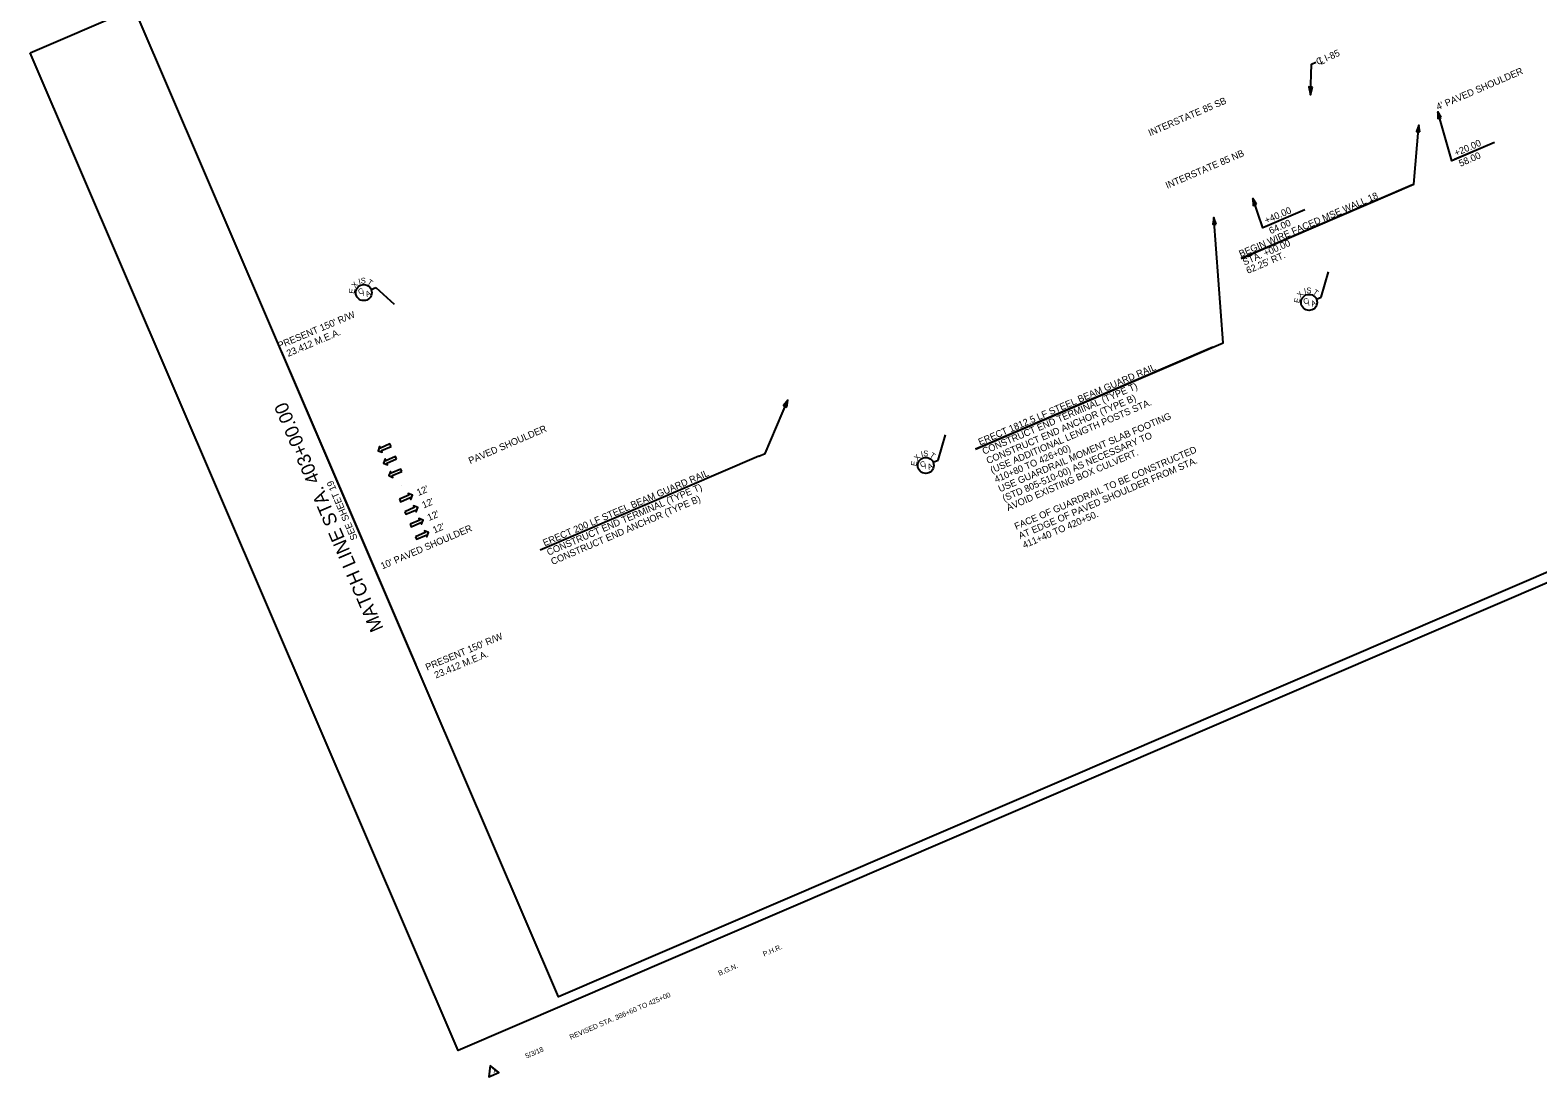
# Model space of a CAD drawing. Extents: x 1618233 to 1620283, y 1101130 to 1102832.
# Drawn here: x 1618233 to 1619562, y 1101130 to 1102053 of the extents above; entities that cross this region are included whole.
import ezdxf

# ---------------------------------------------------------------- set-up
doc = ezdxf.new("R2010")
doc.units = 0
for name, color, linetype in [('RD_DTM_BkLn1', 7, 'Continuous'), ('RD_EX_BldgApp', 7, 'Continuous'), ('RD_EX_DV_TX_Gov', 7, 'Continuous'), ('RD_EX_Fence_Other', 7, 'Continuous'), ('RD_EX_Misc', 7, 'Continuous'), ('RD_EX_Misc_Golf_Teebox', 7, 'Continuous'), ('RD_EX_RailRoad', 7, 'Continuous'), ('RD_EX_VEG', 7, 'Continuous'), ('RD_HC_Data', 7, 'Continuous')]:
    doc.layers.add(name, color=color, linetype=linetype)

msp = doc.modelspace()

# ---------------------------------------------------------------- linework, layer by layer
at = {"layer": 'RD_DTM_BkLn1'}
for p, q in [((1619275.9, 1101773.3), (1619066.6, 1101683.5)), ((1618875.6, 1101677.3), (1618682.7, 1101594.5))]:
    msp.add_line(p, q, dxfattribs=at)
for points in [[(1619066.6, 1101683.5), (1619284.9, 1101777.2), (1619276.9, 1101887.6)], [(1618875.6, 1101677.3), (1618881.1, 1101679.7), (1618901.1, 1101726.7)]]:
    msp.add_lwpolyline(points, dxfattribs=at)
for points in [[(1619278.9, 1101881.9), (1619276.9, 1101887.6), (1619275.8, 1101881.7)], [(1618900.2, 1101720.7), (1618901.1, 1101726.7), (1618897.4, 1101721.9)]]:
    msp.add_lwpolyline(points, close=True, dxfattribs=at)
at = {"layer": 'RD_EX_DV_TX_Gov'}
msp.add_lwpolyline([(1619361.9, 1101995.8), (1619362.8, 1102022.7), (1619366.8, 1102024.5)], dxfattribs=at)
msp.add_lwpolyline([(1619363.8, 1102002.7), (1619360.4, 1102002.8), (1619361.9, 1101995.8)], close=True, dxfattribs=at)
at = {"layer": 'RD_EX_Fence_Other'}
msp.add_lwpolyline([(1618233.1, 1102032.7), (1619772.4, 1102693.3), (1620149.6, 1101814.3), (1618610.4, 1101153.7)], close=True, dxfattribs=at)
at = {"layer": 'RD_EX_Misc'}
for points in [[(1618551.4, 1101685.9), (1618550.4, 1101688.1), (1618542, 1101684.5), (1618541.3, 1101686), (1618539.9, 1101682.2), (1618543.6, 1101680.8), (1618542.9, 1101682.3)], [(1618556.1, 1101674.9), (1618555.2, 1101677.1), (1618546.7, 1101673.4), (1618546.1, 1101674.9), (1618544.6, 1101671.2), (1618548.3, 1101669.7), (1618547.7, 1101671.2)], [(1618560.8, 1101663.8), (1618559.9, 1101666), (1618551.5, 1101662.4), (1618550.8, 1101663.9), (1618549.3, 1101660.2), (1618553, 1101658.7), (1618552.4, 1101660.2)], [(1618558.7, 1101639.4), (1618559.6, 1101637.2), (1618568.1, 1101640.8), (1618568.7, 1101639.3), (1618570.2, 1101643), (1618566.5, 1101644.5), (1618567.1, 1101643)], [(1618563.4, 1101628.4), (1618564.4, 1101626.2), (1618572.8, 1101629.8), (1618573.4, 1101628.3), (1618574.9, 1101632), (1618571.2, 1101633.5), (1618571.8, 1101632)], [(1618568.1, 1101617.4), (1618569.1, 1101615.2), (1618577.5, 1101618.8), (1618578.2, 1101617.3), (1618579.6, 1101621), (1618575.9, 1101622.5), (1618576.6, 1101621)], [(1618572.9, 1101606.3), (1618573.8, 1101604.1), (1618582.3, 1101607.8), (1618582.9, 1101606.3), (1618584.4, 1101610), (1618580.7, 1101611.5), (1618581.3, 1101610)]]:
    msp.add_lwpolyline(points, close=True, dxfattribs=at)
at = {"layer": 'RD_EX_Misc_Golf_Teebox'}
for p, q in [((1619524.3, 1101953.9), (1619488.9, 1101938.7)), ((1619451.9, 1101916.5), (1619300.9, 1101851.7)), ((1619357, 1101894.5), (1619321.5, 1101879.3)), ((1618560.5, 1101651.9), (1618560.5, 1101651.9))]:
    msp.add_line(p, q, dxfattribs=at)
for points in [[(1619524.3, 1101953.9), (1619486.6, 1101937.7), (1619474.2, 1101980.9)], [(1619300.9, 1101851.7), (1619453, 1101917), (1619457.4, 1101969.1)], [(1619357, 1101894.5), (1619320, 1101878.7), (1619311.1, 1101904.4)]]:
    msp.add_lwpolyline(points, dxfattribs=at)
for points in [[(1619477.3, 1101975.8), (1619474.2, 1101980.9), (1619474.3, 1101974.9)], [(1619458.5, 1101963.2), (1619457.4, 1101969.1), (1619455.4, 1101963.5)], [(1619314.5, 1101899.5), (1619311.1, 1101904.4), (1619311.5, 1101898.4)], [(1618638.6, 1101140.3), (1618637.6, 1101130.4), (1618646.5, 1101134.2)]]:
    msp.add_lwpolyline(points, close=True, dxfattribs=at)
at = {"layer": 'RD_EX_RailRoad'}
msp.add_lwpolyline([(1618327.6, 1102066.1), (1619552.6, 1102591.9), (1619566, 1102561.6), (1619719.7, 1102625.9), (1620077.3, 1101792.6), (1618698.9, 1101201)], close=True, dxfattribs=at)
msp.add_lwpolyline([(1618327.6, 1102066.1), (1619552.6, 1102591.9), (1619566, 1102561.6), (1619719.7, 1102625.9), (1620077.3, 1101792.6), (1618698.9, 1101201)], close=True, dxfattribs=at)
at = {"layer": 'RD_EX_VEG'}
msp.add_lwpolyline([(1618573.1, 1101494.1), (1618514, 1101631.9), (1618454.8, 1101769.8)], dxfattribs=at)
at = {"layer": 'RD_HC_Data'}
for p, q in [((1619371.4, 1101817.5), (1619378, 1101839.8)), ((1618533.8, 1101824.3), (1618538, 1101826.1)), ((1618538, 1101826.1), (1618554.1, 1101811.3)), ((1619367.2, 1101815.7), (1619371.4, 1101817.5)), ((1619033.6, 1101673.8), (1619040.2, 1101696.1)), ((1619029.3, 1101672), (1619033.6, 1101673.8))]:
    msp.add_line(p, q, dxfattribs=at)
for centre in [(1618527.3, 1101821.5), (1619360.7, 1101812.9), (1619022.8, 1101669.2)]:
    msp.add_circle(centre, 7.08, dxfattribs=at)

# ---------------------------------------------------------------- texts
at = {"layer": 'RD_DTM_BkLn1'}
for s, p in [('ERECT 1812.5 LF STEEL BEAM GUARD RAIL', (1619070.6, 1101686.8)), ('CONSTRUCT END TERMINAL (TYPE T)', (1619074.1, 1101678.6)), ('CONSTRUCT END ANCHOR (TYPE B)', (1619077.7, 1101670.3)), ('(USE ADDITIONAL LENGTH POSTS STA.', (1619081.2, 1101662)), ('USE GUARDRAIL MOMENT SLAB FOOTING', (1619088.3, 1101645.5)), ('(STD 805-510-00) AS NECESSARY TO ', (1619091.9, 1101637.2)), ('410+80 TO 426+00)', (1619084.8, 1101653.8)), ('AVOID EXISTING BOX CULVERT.', (1619095.4, 1101629)), ('FACE OF GUARDRAIL TO BE CONSTRUCTED', (1619102.5, 1101612.4)), ('AT EDGE OF PAVED SHOULDER FROM STA.', (1619106.1, 1101604.1)), ('ERECT 200 LF STEEL BEAM GUARD RAIL', (1618686.7, 1101597.9)), ('CONSTRUCT END TERMINAL (TYPE T)', (1618690.2, 1101589.6)), ('CONSTRUCT END ANCHOR (TYPE B)', (1618693.8, 1101581.4)), ('411+40 TO 420+50.', (1619109.6, 1101595.9))]:
    msp.add_text(s, height=6, rotation=23.2284, dxfattribs=at).set_placement(p)
at = {"layer": 'RD_EX_BldgApp'}
for s, p in [("PRESENT 150' R/W ", (1618453, 1101771.8)), ('  23.412 M.E.A.', (1618456.6, 1101763.1)), ("PRESENT 150' R/W ", (1618583.2, 1101488.3)), ('  23.412 M.E.A.', (1618586.9, 1101479.6))]:
    msp.add_text(s, height=6, rotation=22.7764, dxfattribs=at).set_placement(p)
at = {"layer": 'RD_EX_DV_TX_Gov'}
for s, p in [('C I-85', (1619368.4, 1102021.9)), ('L', (1619371.2, 1102022.2)), ('INTERSTATE 85 SB', (1619220.5, 1101959.3)), ('INTERSTATE 85 NB', (1619235.7, 1101912.9))]:
    msp.add_text(s, height=6, rotation=23.2217, dxfattribs=at).set_placement(p)
at = {"layer": 'RD_EX_Misc_Golf_Teebox'}
for s, height, rotation, p in [("4' PAVED SHOULDER", 6, 23.2363, (1619474.4, 1101982.2)), ('+20.00', 6, 23.2284, (1619490.3, 1101941.5)), ('58.00', 6, 23.2284, (1619494.3, 1101932.3)), ('BEGIN WIRE FACED MSE WALL 18', 6, 23.23, (1619300.5, 1101852.6)), ('+40.00', 6, 23.2284, (1619323, 1101882.1)), ('64.00', 6, 23.2284, (1619326.9, 1101872.9)), ('STA. +00.00', 6, 23.23, (1619303.7, 1101845.3)), ("62.25' RT.", 6, 23.23, (1619306.8, 1101837.9)), (' PAVED SHOULDER', 6, 23.2363, (1618619.1, 1101669.4)), ("12'", 6, 23.2346, (1618575.4, 1101642.2)), ("12'", 6, 23.2346, (1618580.1, 1101631.2)), ("12'", 6, 23.2346, (1618584.8, 1101620.2)), ("10' PAVED SHOULDER", 6, 23.2363, (1618543.7, 1101577.5)), ("12'", 6, 23.2346, (1618589.6, 1101609.2)), ('P.H.R.', 4.4, 23.2284, (1618880.3, 1101236.3)), ('B.G.N.', 4.4, 23.2284, (1618840.9, 1101219.4)), ('REVISED STA. 386+60 TO 425+00', 4.4, 23.2284, (1618709.8, 1101163.1)), ('5/3/18', 4.4, 23.2284, (1618670.8, 1101146.4)), ('1', 4.4, 23.2284, (1618641.4, 1101133.8))]:
    msp.add_text(s, height=height, rotation=rotation, dxfattribs=at).set_placement(p)
at = {"layer": 'RD_EX_VEG'}
for s, height, p in [('MATCH LINE STA. 403+00.00', 12, (1618544.9, 1101525.6)), ('SEE SHEET 19', 6, (1618522, 1101604.8))]:
    msp.add_text(s, height=height, rotation=113.2284, dxfattribs=at).set_placement(p)
at = {"layer": 'RD_HC_Data'}
for s, rotation, p in [('I', 13.1604, (1618523.2, 1101828.8)), ('S', 1.4399, (1618524.7, 1101829.5)), ('E', 81.809, (1618519, 1101820.3)), ('X', 48.3219, (1618519.7, 1101825.1)), ('C', 23.2251, (1618523.5, 1101819.4)), ('/', 23.2251, (1618527, 1101818.7)), ('A', 23.2251, (1618530, 1101817.6)), ('T', 326.2784, (1618529.8, 1101829.5)), ('X', 46.3697, (1619353.2, 1101816.7)), ('I', 11.2082, (1619356.8, 1101820.3)), ('S', 359.4878, (1619358.4, 1101821)), ('T', 324.3263, (1619363.5, 1101820.8)), ('E', 79.8568, (1619352.3, 1101812)), ('C', 23.2251, (1619356.8, 1101810.8)), ('/', 23.2251, (1619360.4, 1101810)), ('A', 23.2251, (1619363.4, 1101809)), ('X', 46.3697, (1619015.4, 1101673)), ('I', 11.2082, (1619019, 1101676.6)), ('S', 359.4878, (1619020.5, 1101677.3)), ('T', 324.3263, (1619025.6, 1101677.1)), ('E', 79.8568, (1619014.5, 1101668.3)), ('C', 23.2251, (1619019, 1101667.1)), ('/', 23.2251, (1619022.5, 1101666.3)), ('A', 23.2251, (1619025.5, 1101665.3))]:
    msp.add_text(s, height=5, rotation=rotation, dxfattribs=at).set_placement(p)

doc.saveas('drawing.dxf')
